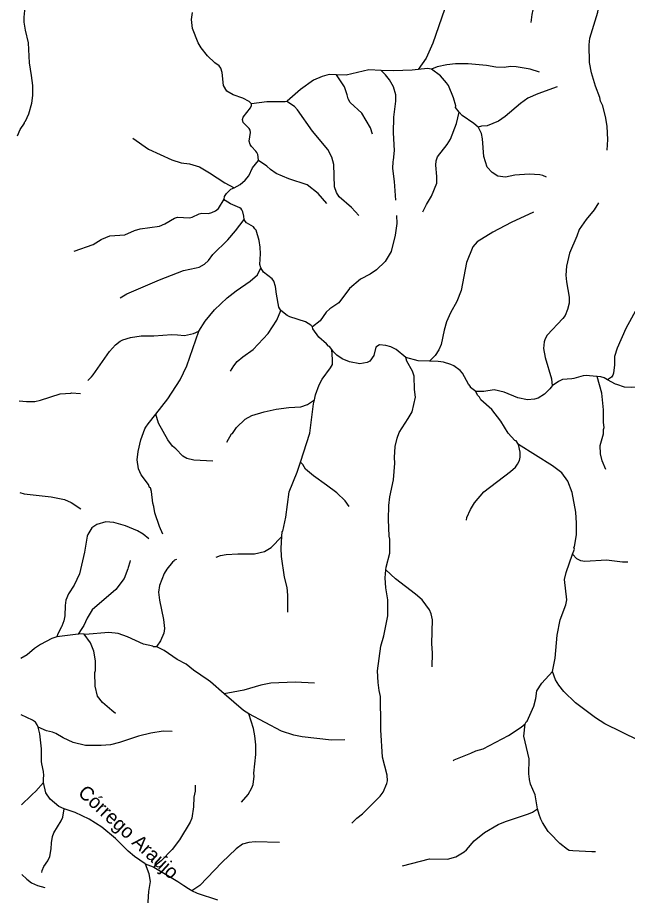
# Model space of a CAD drawing. Extents: x 280.4 to 335.6, y 8893.9 to 8949.5.
# Drawn here: x 280.63 to 287.58, y 8907.81 to 8917.81 of the extents above; entities that cross this region are included whole.
import ezdxf
from ezdxf.enums import TextEntityAlignment as Align

# ---------------------------------------------------------------- set-up
doc = ezdxf.new("R2010")
doc.units = 0
doc.header["$LTSCALE"] = 0.064
doc.layers.add('61', color=7, linetype='Continuous')
doc.layers.add('7', color=7, linetype='Continuous', lineweight=25)

msp = doc.modelspace()

# ---------------------------------------------------------------- linework, layer by layer
at = {"layer": '7'}
msp.add_line((281.3195, 8910.7893), (281.0785, 8910.757), dxfattribs=at)
for points in [[(286.4817, 8917.7536), (286.491, 8917.8458), (286.5052, 8917.8972), (286.5209, 8918.0063), (286.5322, 8918.3059), (286.4846, 8918.6082), (286.452, 8918.7726), (286.4396, 8918.8969), (286.4396, 8919.0249), (286.4791, 8919.2786)], [(287.3448, 8916.3004), (287.3525, 8916.4237), (287.3447, 8916.5685), (287.3319, 8916.6645), (287.2952, 8916.8068), (287.2714, 8916.8597), (287.2634, 8916.9008), (287.2145, 8917.0285), (287.1687, 8917.1809), (287.1465, 8917.2992), (287.1401, 8917.5006), (287.1496, 8917.5769), (287.2391, 8917.8742), (287.2714, 8918.0763), (287.2928, 8918.1346), (287.3875, 8918.2861), (287.4022, 8918.3436), (287.4086, 8918.4026), (287.3737, 8918.5899), (287.3737, 8918.7512), (287.3907, 8918.8361)], [(285.6819, 8918.7372), (285.6753, 8918.6464), (285.643, 8918.418), (285.6238, 8918.3316), (285.5296, 8918.0155), (285.4917, 8917.9037), (285.3613, 8917.5185), (285.2831, 8917.3465), (285.1926, 8917.2195)], [(280.6307, 8916.4643), (280.6616, 8916.5354), (280.7104, 8916.609), (280.7099, 8916.6186), (280.7221, 8916.6317), (280.7589, 8916.7152), (280.794, 8916.8347), (280.8037, 8916.9217), (280.8037, 8917.0354), (280.7906, 8917.1528), (280.7654, 8917.296), (280.7557, 8917.5248), (280.7193, 8917.6687), (280.7047, 8917.7566), (280.7047, 8917.814), (280.7174, 8917.9286), (280.7206, 8918.1448), (280.6985, 8918.1933), (280.6789, 8918.2298)], [(283.2945, 8916.829), (283.2699, 8916.8543), (283.1972, 8916.8937), (283.0869, 8916.9292), (283.0127, 8916.9738), (282.9772, 8917.0356), (282.9626, 8917.1839), (282.9466, 8917.2344), (282.9274, 8917.26), (282.8785, 8917.2947), (282.7959, 8917.3741), (282.7221, 8917.4662), (282.6869, 8917.5226), (282.6232, 8917.688), (282.6126, 8917.787), (282.6239, 8917.8671)], [(284.7722, 8917.2089), (284.6309, 8917.2137), (284.3729, 8917.1547), (284.2635, 8917.158)], [(285.1926, 8917.2195), (285.1263, 8917.2131), (284.9123, 8917.2041), (284.7722, 8917.2089)], [(284.9384, 8915.7307), (284.9234, 8915.9447), (284.9044, 8916.0918), (284.9076, 8916.1704), (284.9137, 8916.186), (284.9234, 8916.2965), (284.9123, 8916.4994), (284.9171, 8916.6772), (284.9394, 8916.857), (284.9394, 8916.9325), (284.9123, 8917.0205), (284.8682, 8917.1015), (284.8232, 8917.1603), (284.7722, 8917.2089)], [(285.3454, 8917.2248), (285.2982, 8917.2296), (285.1926, 8917.2195)], [(286.5745, 8917.1881), (286.4692, 8917.223), (286.3103, 8917.249), (286.2445, 8917.2536), (286.1718, 8917.2409), (286.079, 8917.2456), (285.9718, 8917.2664), (285.7614, 8917.2824), (285.6207, 8917.2824), (285.52, 8917.2735), (285.4113, 8917.2508), (285.3454, 8917.2248)], [(285.6591, 8916.7316), (285.6206, 8916.7871), (285.6235, 8916.8037), (285.5951, 8916.8954), (285.5378, 8917.0354), (285.5181, 8917.0667), (285.448, 8917.1464), (285.3454, 8917.2248)], [(284.2635, 8917.158), (284.1784, 8917.1605), (284.1003, 8917.141), (283.9997, 8917.0989), (283.8549, 8916.9901), (283.7032, 8916.8571), (283.6959, 8916.8556)], [(284.6729, 8916.4822), (284.6493, 8916.5551), (284.5502, 8916.7226), (284.4197, 8916.8428), (284.3945, 8916.886), (284.385, 8916.9322), (284.3541, 8917.0201), (284.2635, 8917.158)], [(286.7761, 8917.0214), (286.5548, 8916.9417), (286.4435, 8916.8929), (286.3577, 8916.8327), (286.1844, 8916.6821), (286.1079, 8916.6321), (285.98, 8916.5791), (285.9161, 8916.5725), (285.8774, 8916.5612)], [(283.3733, 8916.1843), (283.3704, 8916.2245), (283.3664, 8916.2501), (283.3546, 8916.2757), (283.3435, 8916.2899), (283.2959, 8916.3406), (283.2797, 8916.3663), (283.2669, 8916.4015), (283.2837, 8916.5003), (283.279, 8916.5281), (283.2695, 8916.547), (283.2017, 8916.6166), (283.1931, 8916.648), (283.1989, 8916.6765), (283.2825, 8916.7834), (283.2935, 8916.8076), (283.2945, 8916.829)], [(283.6959, 8916.8556), (283.6792, 8916.8523), (283.4706, 8916.8522), (283.2945, 8916.829)], [(284.5195, 8915.5563), (284.433, 8915.6473), (284.2926, 8915.7686), (284.2618, 8915.82), (284.2407, 8915.8846), (284.2322, 8916.1357), (284.2114, 8916.2212), (284.1658, 8916.3062), (283.989, 8916.517), (283.8188, 8916.7605), (283.7848, 8916.7989), (283.6959, 8916.8556)], [(285.2478, 8915.5975), (285.2873, 8915.6818), (285.3468, 8915.775), (285.4062, 8915.9231), (285.4064, 8916.0024), (285.3937, 8916.1309), (285.3984, 8916.1783), (285.4144, 8916.2247), (285.5231, 8916.3645), (285.5633, 8916.4258), (285.6304, 8916.6026), (285.6591, 8916.7316)], [(285.8774, 8916.5612), (285.8279, 8916.6053), (285.696, 8916.6938), (285.6591, 8916.7316)], [(286.6549, 8915.9937), (286.6152, 8916.0124), (286.5802, 8916.0205), (286.4566, 8916.0271), (286.2938, 8916.0174), (286.1867, 8915.994), (286.1017, 8916.004), (286.0352, 8916.0474), (285.9806, 8916.1078), (285.9406, 8916.2277), (285.9274, 8916.43), (285.914, 8916.4886), (285.8793, 8916.5595), (285.8774, 8916.5612)], [(281.9434, 8916.4354), (282.1236, 8916.3123), (282.3877, 8916.1899), (282.4956, 8916.1579), (282.5892, 8916.1467), (282.7036, 8916.1101), (282.8182, 8916.0433), (282.993, 8915.927), (283.0973, 8915.8733)], [(283.0973, 8915.8733), (283.1659, 8915.909), (283.2239, 8915.9588), (283.2632, 8916.0099), (283.3079, 8916.0983), (283.3733, 8916.1843)], [(284.1518, 8915.6945), (284.0562, 8915.8067), (283.9311, 8915.904), (283.7202, 8915.9729), (283.5775, 8916.0348), (283.5114, 8916.0801), (283.4713, 8916.1197), (283.3733, 8916.1843)], [(287.9171, 8916.1618), (287.9286, 8916.1394), (288.0436, 8915.6934), (288.0546, 8915.6718), (288.0582, 8915.6033), (288.0995, 8915.401), (288.106, 8915.2806), (288.0929, 8915.1964), (288.0609, 8915.1038), (288.0084, 8915.0298), (287.8391, 8914.9219), (287.7926, 8914.8227), (287.7482, 8914.6644), (287.6872, 8914.5036), (287.5594, 8914.2701), (287.4599, 8914.0455), (287.4315, 8913.9502), (287.431, 8913.8552), (287.4183, 8913.7608), (287.41, 8913.7382), (287.3955, 8913.7145), (287.3516, 8913.6849)], [(282.9849, 8915.7426), (282.9895, 8915.7732), (283.0094, 8915.8069), (283.0613, 8915.8546), (283.0973, 8915.8733)], [(281.2749, 8915.1507), (281.492, 8915.226), (281.5844, 8915.2842), (281.5906, 8915.2881), (281.6817, 8915.3247), (281.8528, 8915.3378), (281.9637, 8915.3857), (282.0272, 8915.4036), (282.2456, 8915.4351), (282.3075, 8915.461), (282.4197, 8915.5267), (282.4526, 8915.5356), (282.591, 8915.5312), (282.6188, 8915.5373), (282.698, 8915.5761), (282.7293, 8915.5823), (282.8047, 8915.5809), (282.8439, 8915.5905), (282.886, 8915.6112), (282.9179, 8915.6353), (282.9849, 8915.7426)], [(283.2129, 8915.5118), (283.2064, 8915.548), (283.1953, 8915.5983), (283.1863, 8915.6191), (283.1762, 8915.6319), (283.1617, 8915.6441), (283.0573, 8915.6887), (282.996, 8915.7273), (282.9849, 8915.7426)], [(287.247, 8915.6987), (287.1992, 8915.6224), (287.1055, 8915.5124), (287.0266, 8915.3985), (287.0006, 8915.3211), (286.9159, 8915.1258), (286.8845, 8914.9811), (286.8762, 8914.8756), (286.8828, 8914.8018), (286.9146, 8914.6259), (286.9145, 8914.5572), (286.8963, 8914.4853), (286.8665, 8914.4166), (286.8425, 8914.3814), (286.6635, 8914.1926), (286.6399, 8914.1517), (286.6287, 8914.1175), (286.6227, 8914.0406), (286.6409, 8913.9407), (286.7108, 8913.6966), (286.7203, 8913.6172)], [(286.5072, 8915.5925), (286.2534, 8915.4764), (286.0423, 8915.3678), (285.8671, 8915.2545), (285.8175, 8915.2001), (285.745, 8915.0226), (285.6844, 8914.7037), (285.6322, 8914.5771), (285.5613, 8914.4494), (285.5149, 8914.3454), (285.4882, 8914.251), (285.457, 8914.0888), (285.4307, 8914.027), (285.3876, 8913.963), (285.3237, 8913.896)], [(281.7997, 8914.6196), (281.8752, 8914.6628), (282.2469, 8914.8245), (282.5205, 8914.9283), (282.6657, 8914.9618), (282.6992, 8914.9695), (282.76, 8915.0027), (282.8041, 8915.0433), (282.8538, 8915.1133), (283.0252, 8915.2786), (283.1136, 8915.3799), (283.2129, 8915.5118)], [(283.3999, 8914.962), (283.3904, 8914.9998), (283.3992, 8915.1195), (283.3946, 8915.1962), (283.3818, 8915.273), (283.3468, 8915.3882), (283.334, 8915.4059), (283.3168, 8915.4264), (283.24, 8915.4741), (283.2232, 8915.4909), (283.2129, 8915.5118)], [(284.9473, 8915.5563), (284.9522, 8915.4663), (284.9328, 8915.3307), (284.8873, 8915.1456), (284.8165, 8915.0319), (284.7201, 8914.9385), (284.646, 8914.8875), (284.5365, 8914.8307), (284.4107, 8914.724), (284.2917, 8914.5627), (284.1858, 8914.4946), (284.1443, 8914.4559), (284.079, 8914.3575), (283.9898, 8914.2881)], [(282.6955, 8914.2371), (282.7686, 8914.3539), (282.8733, 8914.4837), (283.0177, 8914.6169), (283.1201, 8914.7), (283.2796, 8914.8074), (283.362, 8914.8801), (283.3999, 8914.962)], [(283.6286, 8914.4732), (283.6085, 8914.5134), (283.5804, 8914.6613), (283.5705, 8914.7485), (283.5511, 8914.8067), (283.5309, 8914.8333), (283.4319, 8914.9119), (283.3999, 8914.962)], [(283.0543, 8913.7817), (283.0928, 8913.8446), (283.1327, 8913.8939), (283.1966, 8913.947), (283.3151, 8914.0284), (283.4841, 8914.2119), (283.5832, 8914.3654), (283.6286, 8914.4732)], [(283.9898, 8914.2881), (283.9709, 8914.3062), (283.9098, 8914.3434), (283.7321, 8914.4013), (283.6997, 8914.418), (283.6286, 8914.4732)], [(284.2091, 8914.0283), (284.1838, 8914.0651), (284.1722, 8914.0683), (284.1495, 8914.0963), (284.0626, 8914.169), (283.9943, 8914.2668), (283.9898, 8914.2881)], [(281.43, 8913.6751), (281.4715, 8913.7202), (281.4913, 8913.7417), (281.6787, 8914.0084), (281.7472, 8914.082), (281.7996, 8914.1249), (281.8289, 8914.1398), (281.9182, 8914.1673), (282.04, 8914.1845), (282.184, 8914.1848), (282.3895, 8914.2005), (282.4517, 8914.1966), (282.5339, 8914.1914), (282.6336, 8914.2126), (282.6955, 8914.2371)], [(282.2053, 8913.2951), (282.3406, 8913.4666), (282.4845, 8913.6841), (282.56, 8913.8447), (282.6955, 8914.2371)], [(284.012, 8913.4575), (284.0237, 8913.5132), (284.065, 8913.6272), (284.1015, 8913.6904), (284.1969, 8913.8226), (284.2162, 8913.8601), (284.2197, 8913.9168), (284.2091, 8914.0283)], [(284.6117, 8913.8804), (284.5296, 8913.8667), (284.411, 8913.8906), (284.328, 8913.9227), (284.2662, 8913.9669), (284.2236, 8914.0073), (284.2091, 8914.0283)], [(285.0531, 8913.9371), (284.942, 8914.0297), (284.8818, 8914.0599), (284.8243, 8914.0775), (284.754, 8914.0837), (284.7127, 8914.0565), (284.6882, 8913.9624), (284.6443, 8913.8981), (284.6117, 8913.8804)], [(284.8257, 8911.5195), (284.8278, 8911.5508), (284.869, 8911.7114), (284.869, 8911.8698), (284.8627, 8911.9026), (284.8547, 8912.0928), (284.8595, 8912.2536), (284.8724, 8912.351), (284.9108, 8912.5439), (284.9266, 8912.7341), (284.9236, 8912.7998), (284.9332, 8912.9267), (284.9534, 8913.0204), (284.9779, 8913.0859), (285.0813, 8913.2436), (285.1251, 8913.3218), (285.1632, 8913.4882), (285.1521, 8913.5761), (285.1469, 8913.7272), (285.1278, 8913.7839), (285.0643, 8913.8984), (285.0531, 8913.9371)], [(285.3237, 8913.896), (285.1922, 8913.9011), (285.0531, 8913.9371)], [(285.8522, 8913.5509), (285.7894, 8913.5986), (285.7904, 8913.6079), (285.7678, 8913.6356), (285.6975, 8913.7608), (285.6736, 8913.7911), (285.5983, 8913.844), (285.5652, 8913.8599), (285.4817, 8913.8842), (285.4228, 8913.8921), (285.3237, 8913.896)], [(287.2325, 8913.7228), (287.1861, 8913.7269), (287.144, 8913.7303), (287.1057, 8913.733), (287.0711, 8913.7285), (286.9654, 8913.6993), (286.9433, 8913.6956), (286.8388, 8913.6874), (286.8131, 8913.6788), (286.7908, 8913.6658), (286.7203, 8913.6172)], [(287.3316, 8912.6638), (287.2907, 8912.7623), (287.2693, 8912.842), (287.2683, 8912.9379), (287.3029, 8913.0693), (287.3049, 8913.1204), (287.3127, 8913.1403), (287.3064, 8913.2002), (287.3063, 8913.3418), (287.2837, 8913.5344), (287.2325, 8913.7228)], [(287.3516, 8913.6849), (287.3135, 8913.7058), (287.2759, 8913.7176), (287.2325, 8913.7228)], [(286.7203, 8913.6172), (286.7075, 8913.6008), (286.692, 8913.5827), (286.632, 8913.5231), (286.5586, 8913.475), (286.5203, 8913.4636), (286.4396, 8913.4557), (286.3293, 8913.4804), (286.174, 8913.5433), (286.0582, 8913.5688), (285.9428, 8913.5529), (285.8522, 8913.5509)], [(287.8282, 8913.6086), (287.7573, 8913.6089), (287.6215, 8913.5963), (287.5455, 8913.5996), (287.4548, 8913.6313), (287.4407, 8913.6362), (287.3516, 8913.6849)], [(280.6486, 8913.4451), (280.731, 8913.4363), (280.8264, 8913.4391), (280.8917, 8913.4517), (281.1173, 8913.5241), (281.2368, 8913.5345), (281.2452, 8913.5352), (281.3492, 8913.5306)], [(286.3381, 8912.9472), (286.3083, 8912.9903), (286.2955, 8912.9949), (286.2194, 8913.0789), (286.1364, 8913.2154), (286.0327, 8913.3456), (285.908, 8913.4566), (285.8922, 8913.4872), (285.868, 8913.5113), (285.8522, 8913.5509)], [(283.0158, 8912.9758), (283.0691, 8913.0692), (283.0782, 8913.0739), (283.1254, 8913.143), (283.2242, 8913.2371), (283.2987, 8913.2799), (283.441, 8913.3208), (283.5751, 8913.3495), (283.7193, 8913.3692), (283.859, 8913.3789), (283.9314, 8913.4025), (284.012, 8913.4575)], [(283.854, 8912.7468), (283.9607, 8913.0763), (284.0026, 8913.4125), (284.012, 8913.4575)], [(282.2848, 8911.9254), (282.2459, 8912.0126), (282.1942, 8912.1681), (282.1821, 8912.2422), (282.1696, 8912.2806), (282.1573, 8912.4108), (282.1439, 8912.4529), (282.1353, 8912.4572), (282.1206, 8912.4922), (282.0401, 8912.6037), (282.0068, 8912.6696), (281.9937, 8912.774), (282.0032, 8912.8677), (282.0333, 8913.0014), (282.0807, 8913.1256), (282.0933, 8913.1455), (282.118, 8913.1845), (282.2053, 8913.2951)], [(282.8535, 8912.7598), (282.6384, 8912.7696), (282.5591, 8912.7872), (282.5126, 8912.8133), (282.435, 8912.8972), (282.3961, 8912.9283), (282.3423, 8912.9996), (282.2373, 8913.1909), (282.2053, 8913.2951)], [(285.7455, 8912.0848), (285.7497, 8912.1165), (285.7899, 8912.2089), (285.8342, 8912.2851), (285.9421, 8912.4071), (286.2449, 8912.6419), (286.3011, 8912.6917), (286.3263, 8912.7226), (286.3463, 8912.7647), (286.3563, 8912.8052), (286.3563, 8912.8613), (286.3381, 8912.9472)], [(286.9526, 8911.6989), (286.9724, 8911.7542), (286.9674, 8911.7779), (286.9737, 8911.7833), (286.9961, 8911.9225), (286.9977, 8912.0504), (286.9897, 8912.1768), (286.9479, 8912.4021), (286.8969, 8912.5294), (286.8312, 8912.6253), (286.7249, 8912.7049), (286.3381, 8912.9472)], [(283.6416, 8911.8982), (283.6456, 8911.958), (283.6538, 8911.9602), (283.6855, 8912.1193), (283.7242, 8912.4077), (283.817, 8912.6324), (283.854, 8912.7468)], [(284.4081, 8912.2426), (284.3631, 8912.3059), (284.2666, 8912.396), (284.1504, 8912.4866), (283.9996, 8912.5898), (283.9099, 8912.6684), (283.8816, 8912.7187), (283.854, 8912.7468)], [(280.6549, 8912.4029), (280.7065, 8912.3869), (281.0124, 8912.3517), (281.1645, 8912.3201), (281.2426, 8912.2875), (281.3524, 8912.2144)], [(282.1246, 8911.8731), (282.0623, 8911.9249), (281.9962, 8911.9651), (281.8617, 8912.021), (281.7281, 8912.0608), (281.6344, 8912.0673), (281.5319, 8912.0378), (281.4783, 8911.9995), (281.4323, 8911.9239), (281.4253, 8911.9038), (281.3936, 8911.7228), (281.3349, 8911.4746), (281.2758, 8911.3465), (281.2128, 8911.2461), (281.182, 8911.1759), (281.1716, 8911.1156), (281.17, 8910.9958), (281.1576, 8910.9381), (281.1345, 8910.8783), (281.1297, 8910.8693), (281.0889, 8910.7933), (281.0785, 8910.757)], [(282.8944, 8911.6649), (282.9404, 8911.6818), (283.0049, 8911.6946), (283.1378, 8911.7042), (283.3306, 8911.7027), (283.444, 8911.7276), (283.5185, 8911.7749), (283.6416, 8911.8982)], [(283.7093, 8911.0387), (283.708, 8911.2333), (283.7001, 8911.3189), (283.6713, 8911.4356), (283.6362, 8911.6729), (283.633, 8911.7688), (283.6416, 8911.8982)], [(286.7247, 8910.3637), (286.7559, 8910.516), (286.777, 8910.7759), (286.8111, 8910.9509), (286.8742, 8911.1213), (286.8872, 8911.1796), (286.8588, 8911.4106), (286.878, 8911.4906), (286.9526, 8911.6989)], [(287.5832, 8911.6081), (287.5199, 8911.6064), (287.339, 8911.6306), (287.092, 8911.6147), (287.0479, 8911.6225), (287.0025, 8911.6439), (286.9526, 8911.6989)], [(281.9139, 8911.6268), (281.9106, 8911.6072), (281.8912, 8911.5485), (281.8878, 8911.5331), (281.8435, 8911.4202), (281.7484, 8911.2958), (281.4808, 8911.0632), (281.4227, 8910.9717), (281.3869, 8910.8847), (281.3638, 8910.852), (281.3195, 8910.7893)], [(282.4426, 8911.6398), (282.4197, 8911.6305), (282.4156, 8911.6215), (282.3939, 8911.6084), (282.3302, 8911.5279), (282.3005, 8911.4797), (282.2461, 8911.3428), (282.2368, 8911.266), (282.246, 8911.1761), (282.2941, 8910.9532), (282.3037, 8910.8538), (282.2977, 8910.8006), (282.2591, 8910.7101), (282.2175, 8910.6502), (282.2122, 8910.6426)], [(284.4383, 8908.6331), (284.4935, 8908.6911), (284.5577, 8908.7415), (284.7613, 8908.9433), (284.7941, 8908.9894), (284.837, 8909.0854), (284.8435, 8909.1181), (284.8404, 8909.1832), (284.7892, 8909.3859), (284.7668, 8909.6987), (284.7666, 8909.748), (284.7651, 8910.0786), (284.7495, 8910.1459), (284.738, 8910.2367), (284.7316, 8910.3697), (284.7665, 8910.6503), (284.8034, 8910.7671), (284.8498, 8910.998), (284.8482, 8911.1803), (284.8242, 8911.3154), (284.8196, 8911.4298), (284.8257, 8911.5195)], [(285.3526, 8910.4164), (285.3552, 8910.5694), (285.349, 8910.6813), (285.3584, 8910.9493), (285.341, 8911.0201), (285.3211, 8911.0655), (285.2385, 8911.1779), (285.1629, 8911.2443), (284.9344, 8911.4179), (284.8257, 8911.5195)], [(281.388, 8910.7864), (281.3256, 8910.7901), (281.3195, 8910.7893)], [(282.2122, 8910.6426), (282.1756, 8910.6443), (282.1717, 8910.6502), (282.0664, 8910.6729), (281.8848, 8910.7581), (281.7778, 8910.7954), (281.6713, 8910.807), (281.4008, 8910.7856), (281.388, 8910.7864)], [(281.0785, 8910.757), (281.0203, 8910.7386), (280.8929, 8910.6711), (280.8252, 8910.6236), (280.7414, 8910.5528), (280.6662, 8910.5114)], [(281.7479, 8909.8845), (281.7028, 8909.9164), (281.5967, 8910.0095), (281.5425, 8910.08), (281.5139, 8910.1952), (281.5107, 8910.3505), (281.517, 8910.3743), (281.517, 8910.4855), (281.5, 8910.5951), (281.4626, 8910.6901), (281.388, 8910.7864)], [(282.9835, 8910.1097), (282.8268, 8910.2456), (282.8017, 8910.2629), (282.634, 8910.378), (282.5495, 8910.4469), (282.4475, 8910.4989), (282.3, 8910.6027), (282.2382, 8910.6328), (282.2187, 8910.6423), (282.2122, 8910.6426)], [(286.4131, 8909.7672), (286.4247, 8909.7888), (286.4364, 8909.7971), (286.5115, 8909.9674), (286.5322, 8910.053), (286.5448, 8910.1427), (286.6006, 8910.231), (286.7247, 8910.3637)], [(288.5553, 8909.3261), (288.4498, 8909.3295), (288.2547, 8909.3713), (287.9945, 8909.4551), (287.7061, 8909.5763), (287.3192, 8909.7653), (287.213, 8909.8351), (286.9855, 8910.0069), (286.8542, 8910.1362), (286.7974, 8910.2058), (286.7576, 8910.2687), (286.7247, 8910.3637)], [(284.0121, 8910.228), (283.7921, 8910.2425), (283.5162, 8910.2296), (283.4017, 8910.2074), (283.209, 8910.1482), (283.0869, 8910.1274), (282.9835, 8910.1097)], [(283.265, 8909.8785), (283.2633, 8909.8794), (283.2027, 8909.9195), (282.9835, 8910.1097)], [(280.8649, 8909.7295), (280.8551, 8909.7566), (280.8347, 8909.7839), (280.802, 8909.8079), (280.67, 8909.8694)], [(283.1814, 8908.8723), (283.2582, 8908.9609), (283.3008, 8909.038), (283.3146, 8909.0751), (283.3258, 8909.1702), (283.3229, 8909.2061), (283.3449, 8909.4166), (283.3464, 8909.5274), (283.3351, 8909.6299), (283.318, 8909.714), (283.265, 8909.8785)], [(284.3569, 8909.5838), (284.2063, 8909.5821), (283.8732, 8909.6201), (283.7757, 8909.6378), (283.6377, 8909.6813), (283.265, 8909.8785)], [(282.3905, 8909.6793), (282.2897, 8909.6842), (282.1493, 8909.6608), (282.0076, 8909.6261), (281.7928, 8909.5535), (281.6882, 8909.5263), (281.5827, 8909.5181), (281.4058, 8909.5213), (281.2644, 8909.5533), (281.1515, 8909.6072), (281.066, 8909.6571), (281.0301, 8909.6716), (280.9589, 8909.6866), (280.8649, 8909.7295)], [(280.9247, 8909.0965), (280.927, 8909.1445), (280.9289, 8909.1775), (280.9266, 8909.2221), (280.9056, 8909.3097), (280.9047, 8909.3366), (280.9044, 8909.4819), (280.8838, 8909.6532), (280.8649, 8909.7295)], [(285.5912, 8909.3445), (285.6019, 8909.3552), (285.7945, 8909.4341), (285.8504, 8909.457), (285.935, 8909.481), (286.2234, 8909.634), (286.3659, 8909.7276), (286.4131, 8909.7672)], [(286.5535, 8908.7994), (286.5269, 8908.9587), (286.4745, 8909.0789), (286.461, 8909.1315), (286.4574, 8909.1715), (286.4556, 8909.1917), (286.4587, 8909.366), (286.3981, 8909.6267), (286.4131, 8909.7672)], [(280.6761, 8908.8437), (280.6963, 8908.8639), (280.7686, 8908.9295), (280.7974, 8908.9599), (280.8374, 8908.9999), (280.9247, 8909.0965)], [(281.1605, 8908.7975), (281.0993, 8908.8266), (281.003, 8908.9083), (280.951, 8908.9823), (280.9247, 8909.0965)], [(282.6546, 8909.0676), (282.6521, 8908.9999), (282.6399, 8908.9317), (282.6358, 8908.8201), (282.6141, 8908.6913), (282.5978, 8908.6458), (282.4753, 8908.444), (282.3923, 8908.3354), (282.2679, 8908.2075), (282.1925, 8908.1493), (282.1818, 8908.1309)], [(280.9066, 8908.0737), (280.9099, 8908.0941), (280.9314, 8908.1403), (280.9767, 8908.2058), (280.999, 8908.2537), (281.0148, 8908.3432), (281.0166, 8908.4112), (281.0272, 8908.4818), (281.0433, 8908.5237), (281.1271, 8908.6615), (281.146, 8908.704), (281.1605, 8908.7975)], [(282.0869, 8908.1689), (282.0859, 8908.1713), (281.9642, 8908.2552), (281.8912, 8908.3161), (281.7463, 8908.4604), (281.59, 8908.5893), (281.4466, 8908.6816), (281.2867, 8908.7551), (281.1605, 8908.7975)], [(285.0151, 8908.1508), (285.3226, 8908.2273), (285.5286, 8908.226), (285.6213, 8908.2519), (285.7166, 8908.3089), (285.7439, 8908.333), (285.8297, 8908.4345), (285.9475, 8908.5268), (286.1046, 8908.6195), (286.1879, 8908.6536), (286.4506, 8908.7398), (286.494, 8908.7614), (286.5535, 8908.7994)], [(287.213, 8908.3074), (287.1721, 8908.3092), (286.9538, 8908.3199), (286.9144, 8908.3245), (286.8958, 8908.3344), (286.809, 8908.405), (286.6941, 8908.5207), (286.6741, 8908.5408), (286.6083, 8908.6418), (286.589, 8908.6816), (286.5718, 8908.7342), (286.5535, 8908.7994)], [(283.6159, 8908.4135), (283.3381, 8908.4208), (283.2646, 8908.4153), (283.1932, 8908.3968), (283.1206, 8908.342), (282.9574, 8908.1885), (282.7058, 8907.9257), (282.6157, 8907.8641)], [(282.0391, 8906.4042), (282.055, 8906.4576), (282.0607, 8906.5529), (282.0559, 8906.7521), (282.0608, 8906.8481), (282.0813, 8906.9911), (282.1009, 8907.0511), (282.1404, 8907.2215), (282.1471, 8907.3078), (282.1168, 8907.7396), (282.1248, 8907.8556), (282.1438, 8907.9708), (282.1312, 8908.0572), (282.0869, 8908.1689)], [(282.1818, 8908.1309), (282.1772, 8908.1337), (282.0869, 8908.1689)], [(282.6157, 8907.8641), (282.5774, 8907.8871), (282.5236, 8907.9195), (282.4581, 8907.9663), (282.1818, 8908.1309)], [(280.6809, 8908.0491), (280.7356, 8907.9952), (280.79, 8907.9547), (280.8594, 8907.9247), (280.9398, 8907.9012)], [(282.9128, 8907.7593), (282.6789, 8907.8321), (282.6157, 8907.8641)]]:
    msp.add_lwpolyline(points, dxfattribs=at)

# ---------------------------------------------------------------- texts
at = {"layer": '61'}
msp.add_text('Córrego Araújo', height=0.16, rotation=317.49, dxfattribs=at).set_placement((281.8427, 8908.4758), align=Align.CENTER)

doc.saveas('drawing.dxf')
